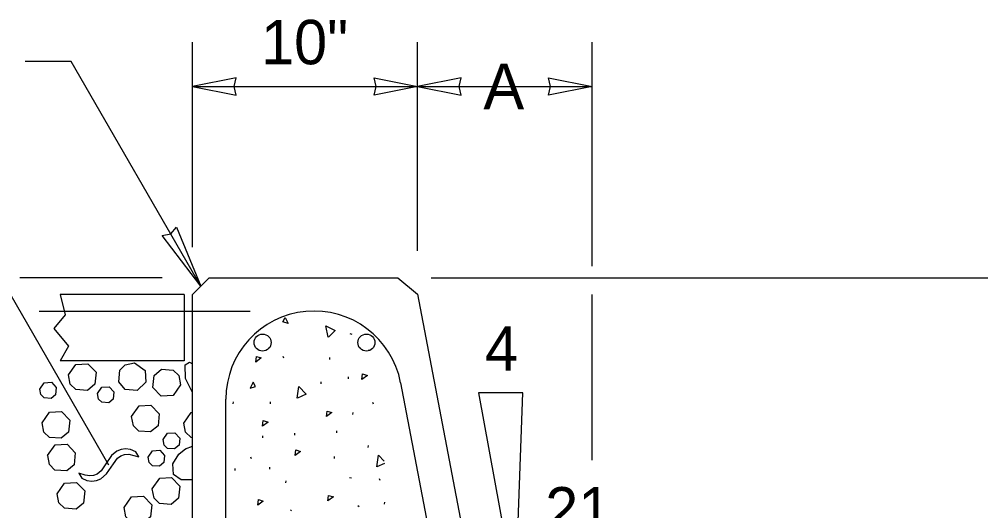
# Model space of a CAD drawing. Extents: x 99862 to 103680, y 99470 to 102076.
# Drawn here: x 102331.5 to 102678.1, y 101323.5 to 101500.8 of the extents above; entities that cross this region are included whole.
import ezdxf

# ---------------------------------------------------------------- set-up
doc = ezdxf.new("R2010")
doc.units = 0
for name, color, linetype in [('Level 10', 7, 'Continuous'), ('Level 13', 7, 'Continuous'), ('Level 15', 7, 'Continuous'), ('Level 2', 7, 'Continuous'), ('Level 20', 7, 'Continuous'), ('Level 7', 7, 'Continuous')]:
    doc.layers.add(name, color=color, linetype=linetype)

msp = doc.modelspace()

# ---------------------------------------------------------------- linework, layer by layer
at = {"layer": 'Level 10'}
for p, q in [((102468.99, 101369.72), (102516.21, 101121.79)), ((102406, 101119.55), (102406, 101363.77))]:
    msp.add_line(p, q, dxfattribs=at)
for centre in [(102419.23, 101384.18), (102456.65, 101384.18)]:
    msp.add_circle(centre, 3.08, dxfattribs=at)
msp.add_arc((102437.77, 101363.77), 31.78, 10.7843, 180, dxfattribs=at)
at = {"layer": 'Level 13'}
for p, q in [((102451.46, 101387.12), (102450.77, 101387.3)), ((102457.27, 101381.42), (102457.91, 101381.59)), ((102426.52, 101379.26), (102426.81, 101378.67)), ((102443.44, 101378.06), (102443.49, 101378.78)), ((102450.19, 101371.11), (102450.24, 101371.83)), ((102440.3, 101369.34), (102440.35, 101370.06)), ((102408.65, 101362.08), (102408.7, 101362.8)), ((102422.02, 101362.08), (102422.07, 101362.8)), ((102458.84, 101362.72), (102459.14, 101362.13)), ((102451.79, 101358.2), (102451.84, 101358.92)), ((102419.3, 101349.83), (102419.35, 101350.55)), ((102430.79, 101350.81), (102430.84, 101351.53)), ((102445.97, 101351.61), (102446.02, 101352.33)), ((102457.32, 101346.34), (102457.37, 101347.06)), ((102414.81, 101343.04), (102415.11, 101342.44)), ((102445.14, 101342.43), (102445.19, 101343.15)), ((102409.33, 101338.02), (102409.38, 101338.74)), ((102421.79, 101338.49), (102421.84, 101339.21)), ((102427.63, 101333.61), (102427.68, 101334.33)), ((102451.22, 101335.26), (102450.52, 101335.45)), ((102461.21, 101335.2), (102461.5, 101334.6)), ((102453.55, 101325.43), (102453.98, 101325.12)), ((102463.18, 101325.87), (102463.23, 101326.59)), ((102429.23, 101323.91), (102429.66, 101323.59))]:
    msp.add_line(p, q, dxfattribs=at)
for points in [[(102428.5, 101391.03), (102426.55, 101391.61), (102427.41, 101393.23), (102428.5, 101391.03)], [(102442.9, 101386.1), (102442.02, 101390.23), (102445.41, 101388.58), (102442.96, 101386.15)], [(102416.78, 101377.16), (102416.98, 101379.18), (102418.73, 101378.65), (102416.78, 101377.16)], [(102455.04, 101370.85), (102455.24, 101372.87), (102456.99, 101372.34), (102455.04, 101370.85)], [(102414.76, 101367.76), (102416.7, 101368.34), (102415.85, 101369.96), (102414.76, 101367.76)], [(102431.68, 101364.1), (102432.26, 101368.29), (102434.88, 101365.58), (102431.75, 101364.13)], [(102442.29, 101357.48), (102442.49, 101359.5), (102444.24, 101358.97), (102442.29, 101357.48)], [(102419.24, 101354.02), (102419.44, 101356.04), (102421.19, 101355.51), (102419.24, 101354.02)], [(102430.95, 101343.44), (102431.15, 101345.46), (102432.91, 101344.93), (102430.95, 101343.44)], [(102460.38, 101339.35), (102460.96, 101343.54), (102463.01, 101341.43)], [(102463.16, 101340.63), (102460.45, 101339.37)], [(102442.8, 101327.08), (102443, 101329.1), (102444.76, 101328.57), (102442.8, 101327.08)], [(102417.51, 101325.55), (102417.71, 101327.57), (102419.46, 101327.04), (102417.51, 101325.55)]]:
    msp.add_lwpolyline(points, dxfattribs=at)
at = {"layer": 'Level 15'}
for p, q in [((102394, 101418.52), (102394, 101492.52)), ((102475.12, 101417.23), (102475.12, 101492.52)), ((102538, 101411.78), (102538, 101492.52)), ((102350.24, 101485.53), (102333.6, 101485.53)), ((102397, 101404.55), (102350.24, 101485.53)), ((102394, 101476.52), (102475.12, 101476.52)), ((102475.12, 101476.52), (102538, 101476.52)), ((102363.8, 101340.04), (102308.04, 101436.6)), ((102383.03, 101407.55), (102331.75, 101407.55)), ((102479.98, 101407.55), (102844.25, 101407.55)), ((102538, 101341.84), (102538, 101401.55)), ((102338.68, 101395.55), (102414.78, 101395.55))]:
    msp.add_line(p, q, dxfattribs=at)
for points in [[(102394, 101476.52), (102409.72, 101473.43), (102408.99, 101476.52), (102409.72, 101479.6)], [(102475.12, 101476.52), (102459.39, 101473.43), (102460.12, 101476.52), (102459.39, 101479.6)], [(102475.12, 101476.52), (102490.84, 101473.43), (102490.12, 101476.52), (102490.84, 101479.6)], [(102538, 101476.52), (102522.27, 101473.43), (102523, 101476.52), (102522.27, 101479.6)], [(102397, 101404.55), (102383, 101422.82), (102386.11, 101423.4), (102388.17, 101425.81)], [(102510.38, 101293.13), (102513.09, 101366.08), (102497.09, 101366.08)]]:
    msp.add_lwpolyline(points, close=True, dxfattribs=at)
at = {"layer": 'Level 2'}
for p, q in [((102391, 101401.55), (102346.24, 101401.55)), ((102391, 101401.55), (102391, 101377.55)), ((102391, 101377.55), (102346.24, 101377.55))]:
    msp.add_line(p, q, dxfattribs=at)
for points in [[(102394, 101071.55), (102394, 101401.55), (102400, 101407.55), (102468, 101407.55), (102475.12, 101401.65), (102538, 101071.55)], [(102346.24, 101401.55), (102348.05, 101394.22), (102343.96, 101389.26), (102349.21, 101382.84), (102346.24, 101377.55)]]:
    msp.add_lwpolyline(points, dxfattribs=at)
at = {"layer": 'Level 20'}
for p, q in [((102364.75, 101343.49), (102362.48, 101340.08)), ((102366.68, 101345.03), (102364.75, 101343.49)), ((102368.21, 101345.68), (102366.68, 101345.03)), ((102366.92, 101342.45), (102368.08, 101343.4)), ((102368.08, 101343.4), (102369.42, 101343.88)), ((102369.81, 101345.85), (102368.21, 101345.68)), ((102369.42, 101343.88), (102371.06, 101343.94)), ((102371.57, 101345.58), (102369.81, 101345.85)), ((102371.06, 101343.94), (102374.64, 101343.01)), ((102373.59, 101344.84), (102371.57, 101345.58)), ((102374.64, 101343.01), (102373.58, 101344.84)), ((102362.48, 101340.08), (102361.02, 101338)), ((102363.01, 101336.84), (102365.53, 101340.46)), ((102365.53, 101340.46), (102366.92, 101342.45)), ((102352.95, 101337.11), (102354.01, 101335.28)), ((102355.26, 101336.37), (102352.95, 101337.1)), ((102356.97, 101336.1), (102355.26, 101336.37)), ((102358.33, 101336.24), (102356.97, 101336.1)), ((102359.56, 101336.74), (102358.33, 101336.24)), ((102361.02, 101338), (102359.56, 101336.74)), ((102360.93, 101335.09), (102363.01, 101336.84)), ((102354.01, 101335.27), (102355.84, 101334.51)), ((102355.84, 101334.51), (102357.61, 101334.22)), ((102357.61, 101334.22), (102359.3, 101334.41)), ((102359.3, 101334.41), (102360.93, 101335.09))]:
    msp.add_line(p, q, dxfattribs=at)
at = {"layer": 'Level 7'}
for points in [[(102349.22, 101372.5), (102351.91, 101376.32), (102356.21, 101376.57), (102359.19, 101373.47), (102358.76, 101369.14), (102356.11, 101366.93), (102351.87, 101367.24), (102349.87, 101369.17), (102349.23, 101372.5)], [(102373.02, 101376.85), (102376.84, 101374.16), (102377.09, 101369.87), (102373.99, 101366.88), (102369.66, 101367.32), (102367.45, 101369.97), (102367.76, 101374.21), (102369.69, 101376.2), (102373.02, 101376.85)], [(102389.65, 101368.97), (102386.96, 101365.15), (102382.66, 101364.9), (102379.68, 101368), (102380.11, 101372.33), (102382.76, 101374.54), (102387, 101374.23), (102389, 101372.3), (102389.64, 101368.97)], [(102393.95, 101366.14), (102391.4, 101371.24), (102391.32, 101376.1), (102392.85, 101377.11), (102393.95, 101376.54)], [(102338.89, 101367.41), (102340.5, 101369.71), (102343.08, 101369.85), (102344.87, 101368), (102344.61, 101365.39), (102343.02, 101364.07), (102340.47, 101364.25), (102339.28, 101365.41), (102338.89, 101367.41)], [(102359.67, 101365.82), (102361.29, 101368.11), (102363.86, 101368.26), (102365.65, 101366.4), (102365.39, 101363.8), (102363.8, 101362.48), (102361.26, 101362.66), (102360.06, 101363.82), (102359.67, 101365.82)], [(102371.99, 101357.54), (102374.68, 101361.37), (102378.97, 101361.61), (102381.96, 101358.52), (102381.53, 101354.18), (102378.87, 101351.97), (102374.63, 101352.28), (102372.64, 101354.22), (102371.99, 101357.54)], [(102339.73, 101355.26), (102342.42, 101359.09), (102346.71, 101359.33), (102349.7, 101356.24), (102349.27, 101351.9), (102346.61, 101349.7), (102342.37, 101350), (102340.38, 101351.94), (102339.73, 101355.26)], [(102390.79, 101355.18), (102393.48, 101359.01), (102394, 101359.04)], [(102394, 101349.88), (102393.43, 101349.92), (102391.44, 101351.86), (102390.79, 101355.18)], [(102383.37, 101349.18), (102384.99, 101351.48), (102387.56, 101351.63), (102389.36, 101349.77), (102389.1, 101347.17), (102387.51, 101345.84), (102384.96, 101346.03), (102383.76, 101347.19), (102383.38, 101349.18)], [(102341.74, 101343.5), (102344.43, 101347.32), (102348.73, 101347.57), (102351.71, 101344.47), (102351.28, 101340.14), (102348.63, 101337.93), (102344.39, 101338.24), (102342.39, 101340.17), (102341.75, 101343.5)], [(102391.4, 101345.84), (102394, 101346.88)], [(102377.94, 101342.91), (102379.55, 101345.21), (102382.13, 101345.35), (102383.92, 101343.5), (102383.66, 101340.89), (102382.07, 101339.57), (102379.52, 101339.76), (102378.33, 101340.92), (102377.94, 101342.91)], [(102394, 101334.75), (102389.83, 101334.68), (102387.1, 101336.62), (102386.84, 101340.49), (102389.06, 101343.95), (102391.6, 101345.97)], [(102345.15, 101329.7), (102347.83, 101333.52), (102352.13, 101333.77), (102355.11, 101330.68), (102354.68, 101326.34), (102352.03, 101324.13), (102347.79, 101324.44), (102345.8, 101326.37), (102345.15, 101329.7)], [(102379.44, 101331.42), (102382.13, 101335.24), (102386.42, 101335.49), (102389.41, 101332.39), (102388.97, 101328.06), (102386.32, 101325.85), (102382.08, 101326.16), (102380.09, 101328.09), (102379.44, 101331.42)], [(102369.32, 101324.69), (102372.01, 101328.52), (102376.31, 101328.76), (102379.29, 101325.67), (102378.86, 101321.33), (102376.21, 101319.13), (102371.97, 101319.43), (102369.97, 101321.37), (102369.33, 101324.69)]]:
    msp.add_lwpolyline(points, dxfattribs=at)

# ---------------------------------------------------------------- texts
at = {"layer": 'Level 15'}
msp.add_text('A', height=16.5, dxfattribs=at).set_placement((102498.81, 101468.27))
at = {"layer": 'Level 20'}
msp.add_text('10"', height=16, rotation=360, dxfattribs=at).set_placement((102418.69, 101484.52))
for s, p in [('4', (102499.42, 101374.08)), ('21', (102521.11, 101316.08))]:
    msp.add_text(s, height=16, dxfattribs=at).set_placement(p)

doc.saveas('drawing.dxf')
